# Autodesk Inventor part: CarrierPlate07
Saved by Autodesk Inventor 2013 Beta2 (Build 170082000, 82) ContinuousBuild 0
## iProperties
Created: 2008-02
Part Number: CarrierPlate07
Document SubType Name: Modeling
Designer: grh
Density: 1 g/cm^3
Material: Generic
Author: grh
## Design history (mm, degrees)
sketch "Sketch1"
  geometry: L1 (48.514, 0)-(0, 0); L2 (0, 0)-(37.164, 31.184); L3 (8.424, 47.777)-(0, 0); L4 (-24.257, 42.014)-(0, 0); L5 (-45.588, 16.593)-(0, 0); L6 (-45.588, -16.593)-(0, 0); L7 (-24.257, -42.014)-(0, 0); C1 r 53.34 at (0, 0)
  constraints: 14 end point, 6 equal length, 1 centre point, 1 horizontal, 1 other
  dimensions: "BlankDiameter" = 106.68 diameter of C1; "PlanetRadius" = 48.514 distance of L1.start L1.end; "Angle1" = 40 deg angle of L2 L1; "Angle2" = 40 deg angle of L3 L2; "Angle3" = 40 deg angle of L4 L3; "Angle4" = 40 deg angle of L5 L4; "Angle5" = 40 deg angle of L6 L5; "Angle7" = 40 deg angle of L7 L6
extrude "Extrusion1" new body sketch "Sketch1" stored distance "d9" = 13.97; taper "d10" = 0 deg
node "Axis1"
node "Axis2"
node "Axis3"
node "Axis4"
node "Axis5"
node "Axis6"
node "Axis7"
node "Axis8"
body "Solid1"
